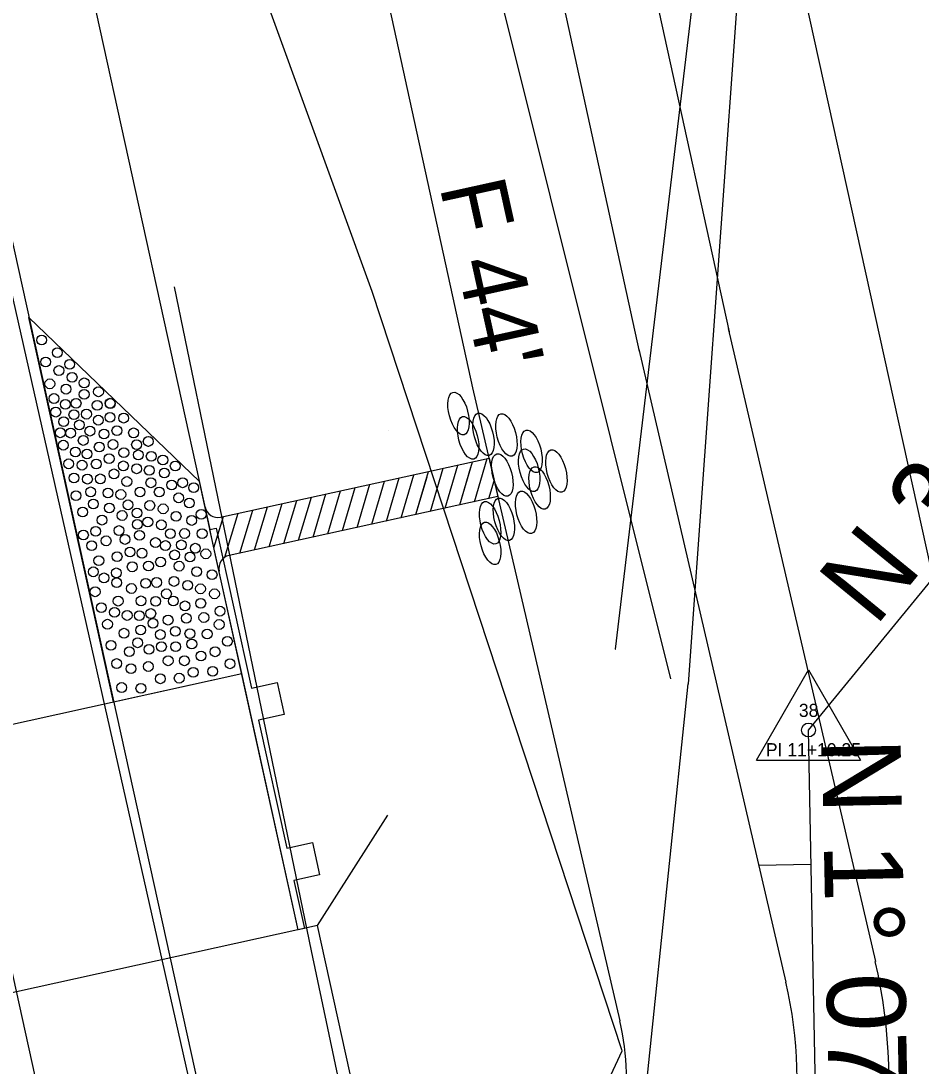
# Model space of a CAD drawing. Extents: x 2519952 to 2531965, y 848341 to 887632.
# Drawn here: x 2522935.4 to 2523004, y 863099 to 863178.7 of the extents above; entities that cross this region are included whole.
import ezdxf

# ---------------------------------------------------------------- set-up
doc = ezdxf.new("R2010")
doc.units = 0
for name, color, linetype in [('RD_EV_JW', 7, 'Continuous'), ('RD_EX_DV_Prop', 7, 'Continuous'), ('RD_EX_GuardRail', 7, 'Continuous'), ('RD_EX_H2O', 7, 'Continuous'), ('RD_EX_Misc', 7, 'Continuous'), ('RD_EX_Road', 7, 'Continuous'), ('RD_EX_RW', 7, 'Continuous'), ('RD_EX_VEG', 7, 'Continuous'), ('RD_HC_Cl', 7, 'Continuous'), ('RD_HC_Data', 7, 'Continuous'), ('RD_HC_Data_Tic', 7, 'Continuous'), ('RD_HC_txCode', 7, 'Continuous'), ('RD_PD_BCA', 7, 'Continuous'), ('RD_PD_Bridge', 7, 'Continuous'), ('RD_PD_CstnLmt', 7, 'Continuous'), ('RD_PD_DR_ErosCtrl', 7, 'Continuous'), ('RD_PD_Final_TrvlWay', 7, 'Continuous'), ('RD_PD_GR', 7, 'Continuous'), ('RD_PD_PaveShd', 7, 'Continuous'), ('RD_PD_TX_CstnLmt', 7, 'Continuous'), ('RD_SMD_Locator', 7, 'Continuous')]:
    doc.layers.add(name, color=color, linetype=linetype)

# ---------------------------------------------------------------- blocks, each defined once
blk = doc.blocks.new('TBC1')
at = {"layer": 'RD_PD_GR'}
blk.add_lwpolyline([(12.5, 2.5), (15, 2.5), (15, 0.492), (25, 0.492), (25, 2.5), (27.5, 2.5), (27.5, 0.492), (31.25, 0.492), (31.25, 0), (0, 0), (0, 0.492), (12.5, 0.492)], close=True, dxfattribs=at)

msp = doc.modelspace()

# ---------------------------------------------------------------- linework, layer by layer
at = {"layer": 'RD_EV_JW'}
msp.add_lwpolyline([(2522920.527, 863055.569), (2522967.569, 863070.747), (2522981.274, 863100.176), (2522962.21, 863158.087), (2522937.169, 863227.102), (2522907.556, 863365.862), (2522890.04, 863438.415), (2522867.996, 863538.839), (2522858.074, 863583.559), (2522887.186, 863587.355), (2522916.656, 863593.291)], dxfattribs=at)
at = {"layer": 'RD_EX_DV_Prop'}
msp.add_line((2522989.51, 863206.261), (2523054.026, 862913.28), dxfattribs=at)
at = {"layer": 'RD_EX_GuardRail'}
msp.add_lwpolyline([(2522963.145, 863081.451), (2522957.598, 863107.795), (2522947.155, 863158.431)], dxfattribs=at)
at = {"layer": 'RD_EX_H2O'}
for points in [[(2523224.216, 863086.689), (2523195.729, 863135.324), (2523216.583, 863174.261), (2523191.314, 863213.173), (2523142.614, 863247.836), (2523099.968, 863233.365), (2523064.196, 863226.552), (2523034.343, 863193.635), (2523009.678, 863201.78), (2522990.024, 863180.338), (2522986.288, 863128.151)], [(2522898.268, 863069.037), (2522903.054, 863060.382), (2522975.719, 863073.829), (2522981.786, 863084.838), (2522986.288, 863128.151)]]:
    msp.add_lwpolyline(points, dxfattribs=at)
at = {"layer": 'RD_EX_Misc'}
msp.add_lwpolyline([(2523225.665, 863086.89), (2523196.661, 863135.687), (2523217.305, 863174.605), (2523198.882, 863204.707), (2523192.281, 863214.105), (2523142.89, 863249.517), (2523099.598, 863234.813), (2523063.493, 863227.785), (2523034.22, 863194.205), (2523009.317, 863204.046), (2522987.011, 863183.473), (2522980.744, 863130.816)], dxfattribs=at)
at = {"layer": 'RD_EX_Road'}
msp.add_line((2522952.137, 863080.85), (2522930.599, 863176.326), dxfattribs=at)
at = {"layer": 'RD_EX_RW'}
msp.add_line((2522989.511, 863206.258), (2523054.026, 862913.278), dxfattribs=at)
at = {"layer": 'RD_EX_VEG'}
msp.add_lwpolyline([(2522984.982, 863128.55), (2522971.227, 863183.645), (2522892.381, 863575.764), (2522846.466, 863797.775)], dxfattribs=at)
at = {"layer": 'RD_HC_Cl'}
for p, q in [((2522800.525, 863715.741), (2523357.118, 861188.096)), ((2522995.466, 863124.639), (2523043.023, 863182.772)), ((2522996.539, 863069.862), (2522995.466, 863124.639))]:
    msp.add_line(p, q, dxfattribs=at)
at = {"layer": 'RD_HC_Data'}
for p, q in [((2522991.495, 863122.346), (2522995.467, 863129.226)), ((2522995.467, 863129.226), (2522999.435, 863122.346)), ((2522991.495, 863122.346), (2522999.435, 863122.346))]:
    msp.add_line(p, q, dxfattribs=at)
msp.add_circle((2522995.466, 863124.639), 0.529, dxfattribs=at)
at = {"layer": 'RD_HC_Data_Tic'}
msp.add_line((2522995.667, 863114.384), (2522991.667, 863114.306), dxfattribs=at)
at = {"layer": 'RD_PD_BCA'}
for p, q in [((2522984.06, 863179.459), (2522989.408, 863155.01)), ((2522989.352, 863155.259), (2523000.561, 863106.989))]:
    msp.add_line(p, q, dxfattribs=at)
msp.add_arc((2522961.597, 863097.941), 40, 282.41848, 13.07237, dxfattribs=at)
at = {"layer": 'RD_PD_Bridge'}
for p, q in [((2522909.296, 863119.48), (2522952.266, 863128.942)), ((2522956.567, 863109.41), (2522952.266, 863128.942)), ((2522958.032, 863109.733), (2522963.417, 863118.159))]:
    msp.add_line(p, q, dxfattribs=at)
for points in [[(2522958.032, 863109.733), (2522912.132, 863099.626)], [(2522985.989, 862982.775), (2522958.032, 863109.733)]]:
    msp.add_lwpolyline(points, dxfattribs=at)
at = {"layer": 'RD_PD_CstnLmt'}
for p, q in [((2522948.501, 863248.426), (2522969.87, 863150.736)), ((2522969.87, 863150.736), (2522981.079, 863102.465))]:
    msp.add_line(p, q, dxfattribs=at)
msp.add_arc((2522961.597, 863097.941), 20, 282.41848, 13.07237, dxfattribs=at)
at = {"layer": 'RD_PD_DR_ErosCtrl'}
for p, q in [((2522961.201, 863251.204), (2522982.57, 863153.514)), ((2522982.534, 863153.676), (2522993.742, 863105.405))]:
    msp.add_line(p, q, dxfattribs=at)
msp.add_arc((2522961.597, 863097.941), 33, 282.41848, 13.07237, dxfattribs=at)
at = {"layer": 'RD_PD_Final_TrvlWay'}
msp.add_line((2522901.104, 863314.786), (2523175.293, 862069.617), dxfattribs=at)
at = {"layer": 'RD_PD_GR'}
msp.add_line((2522901.461, 863359.665), (2522949.847, 863139.929), dxfattribs=at)
at = {"layer": 'RD_PD_PaveShd'}
for p, q in [((2522936.049, 863156.09), (2522949.041, 863143.592)), ((2522942.5, 863126.792), (2522936.049, 863156.09)), ((2522950.662, 863140.876), (2522971.117, 863145.369)), ((2522967.763, 863141.561), (2522968.747, 863144.849)), ((2522967.763, 863141.561), (2522968.747, 863144.849)), ((2522968.881, 863141.807), (2522969.865, 863145.094)), ((2522969.998, 863142.052), (2522970.982, 863145.34)), ((2522969.998, 863142.052), (2522970.982, 863145.34)), ((2522971.117, 863145.369), (2522971.795, 863142.447)), ((2522964.412, 863140.825), (2522965.395, 863144.113)), ((2522964.412, 863140.825), (2522965.395, 863144.113)), ((2522965.529, 863141.07), (2522966.513, 863144.358)), ((2522966.646, 863141.316), (2522967.63, 863144.603)), ((2522966.646, 863141.316), (2522967.63, 863144.603)), ((2522968.881, 863141.807), (2522969.743, 863144.689)), ((2522949.686, 863140.662), (2522949.041, 863143.592)), ((2522961.06, 863140.089), (2522962.044, 863143.376)), ((2522961.06, 863140.089), (2522962.044, 863143.376)), ((2522962.177, 863140.334), (2522963.161, 863143.622)), ((2522962.177, 863140.334), (2522963.161, 863143.622)), ((2522963.294, 863140.579), (2522964.278, 863143.867)), ((2522963.294, 863140.579), (2522964.278, 863143.867)), ((2522965.529, 863141.07), (2522966.391, 863143.953)), ((2522971.115, 863142.297), (2522971.518, 863143.642)), ((2522971.115, 863142.297), (2522971.518, 863143.642)), ((2522971.795, 863142.447), (2522951.308, 863137.947)), ((2522956.591, 863139.107), (2522957.575, 863142.395)), ((2522956.591, 863139.107), (2522957.575, 863142.395)), ((2522957.708, 863139.352), (2522958.692, 863142.64)), ((2522957.708, 863139.352), (2522958.692, 863142.64)), ((2522958.825, 863139.598), (2522959.809, 863142.885)), ((2522958.825, 863139.598), (2522959.809, 863142.885)), ((2522959.942, 863139.843), (2522960.926, 863143.131)), ((2522959.942, 863139.843), (2522960.926, 863143.131)), ((2522953.239, 863138.371), (2522954.223, 863141.658)), ((2522953.239, 863138.371), (2522954.223, 863141.658)), ((2522954.356, 863138.616), (2522955.34, 863141.904)), ((2522954.356, 863138.616), (2522955.34, 863141.904)), ((2522955.473, 863138.861), (2522956.457, 863142.149)), ((2522950.155, 863138.531), (2522950.871, 863140.922)), ((2522950.984, 863137.812), (2522951.988, 863141.167)), ((2522952.121, 863138.125), (2522953.105, 863141.413)), ((2522952.121, 863138.125), (2522953.105, 863141.413)), ((2522950.331, 863137.732), (2522949.686, 863140.662)), ((2522952.266, 863128.942), (2522950.331, 863137.732)), ((2522942.5, 863126.792), (2522952.266, 863128.942))]:
    msp.add_line(p, q, dxfattribs=at)
for centre in [(2522937.026, 863154.38), (2522938.215, 863153.422), (2522938.215, 863153.422), (2522937.328, 863152.707), (2522937.328, 863152.707), (2522939.153, 863152.527), (2522939.153, 863152.527), (2522938.336, 863152.051), (2522938.336, 863152.051), (2522937.644, 863151.041), (2522937.644, 863151.041), (2522939.341, 863151.538), (2522939.341, 863151.538), (2522940.263, 863151.112), (2522938.881, 863150.635), (2522938.881, 863150.635), (2522940.262, 863150.234), (2522940.262, 863150.234), (2522941.353, 863150.434), (2522941.353, 863150.434), (2522937.958, 863149.919), (2522937.958, 863149.919), (2522938.831, 863149.481), (2522938.831, 863149.481), (2522939.645, 863149.556), (2522939.645, 863149.556), (2522941.254, 863149.406), (2522941.254, 863149.406), (2522942.237, 863149.562), (2522942.261, 863149.538), (2522938.097, 863148.885), (2522938.097, 863148.885), (2522939.479, 863148.685), (2522939.479, 863148.685), (2522940.437, 863148.729), (2522940.437, 863148.729), (2522942.224, 863148.489), (2522942.224, 863148.489), (2522943.268, 863148.425), (2522943.268, 863148.425), (2522938.693, 863148.152), (2522938.693, 863148.152), (2522939.896, 863147.91), (2522939.896, 863147.91), (2522941.339, 863148.27), (2522941.339, 863148.27), (2522938.44, 863147.306), (2522938.44, 863147.306), (2522939.235, 863147.281), (2522939.235, 863147.281), (2522940.699, 863147.434), (2522940.699, 863147.434), (2522941.77, 863147.208), (2522941.77, 863147.208), (2522942.756, 863147.474), (2522942.756, 863147.474), (2522944.027, 863147.3), (2522944.027, 863147.3), (2522938.676, 863146.361), (2522938.676, 863146.361), (2522940.191, 863146.723), (2522940.191, 863146.723), (2522941.41, 863146.217), (2522941.41, 863146.217), (2522942.453, 863146.413), (2522942.453, 863146.413), (2522944.255, 863146.405), (2522944.255, 863146.405), (2522945.145, 863146.647), (2522945.156, 863146.645), (2522939.595, 863145.838), (2522939.595, 863145.838), (2522940.473, 863145.694), (2522940.473, 863145.694), (2522942.164, 863145.329), (2522942.164, 863145.329), (2522943.284, 863145.786), (2522943.284, 863145.786), (2522944.392, 863145.62), (2522944.392, 863145.62), (2522945.373, 863145.513), (2522945.373, 863145.513), (2522946.259, 863145.227), (2522946.259, 863145.227), (2522939.082, 863144.94), (2522939.082, 863144.94), (2522940.102, 863144.836), (2522940.102, 863144.836), (2522941.181, 863144.926), (2522941.181, 863144.926), (2522943.252, 863144.782), (2522943.252, 863144.782), (2522944.262, 863144.563), (2522944.262, 863144.563), (2522945.218, 863144.443), (2522945.218, 863144.443), (2522947.201, 863144.78), (2522947.201, 863144.78), (2522939.482, 863143.863), (2522939.482, 863143.863), (2522940.51, 863143.773), (2522940.51, 863143.773), (2522941.487, 863143.791), (2522941.487, 863143.791), (2522942.531, 863144.171), (2522942.531, 863144.171), (2522946.377, 863144.241), (2522946.377, 863144.241), (2522943.514, 863143.588), (2522943.514, 863143.588), (2522945.347, 863143.494), (2522945.347, 863143.494), (2522946.932, 863143.331), (2522946.932, 863143.331), (2522947.767, 863143.494), (2522947.767, 863143.494), (2522948.606, 863143.12), (2522948.606, 863143.12), (2522948.606, 863143.12), (2522939.637, 863142.514), (2522939.637, 863142.514), (2522940.756, 863142.8), (2522940.756, 863142.8), (2522942.075, 863142.716), (2522942.075, 863142.716), (2522943.053, 863142.599), (2522943.053, 863142.599), (2522944.517, 863142.792), (2522944.517, 863142.792), (2522945.983, 863142.787), (2522945.983, 863142.787), (2522947.464, 863142.345), (2522947.464, 863142.345), (2522940.151, 863141.265), (2522940.151, 863141.265), (2522940.957, 863141.882), (2522940.957, 863141.882), (2522942.185, 863141.566), (2522942.185, 863141.566), (2522943.604, 863141.814), (2522943.604, 863141.814), (2522945.263, 863141.762), (2522945.263, 863141.762), (2522946.283, 863141.509), (2522946.283, 863141.509), (2522948.278, 863141.956), (2522948.278, 863141.956), (2522941.621, 863140.649), (2522941.621, 863140.649), (2522943.152, 863140.998), (2522943.152, 863140.998), (2522944.287, 863141.196), (2522944.287, 863141.196), (2522945.114, 863140.504), (2522945.114, 863140.504), (2522947.269, 863140.935), (2522947.269, 863140.935), (2522948.457, 863140.621), (2522948.457, 863140.621), (2522949.18, 863141.087), (2522949.18, 863141.087), (2522941.137, 863139.792), (2522941.137, 863139.792), (2522942.912, 863139.85), (2522942.912, 863139.85), (2522944.314, 863140.32), (2522944.314, 863140.32), (2522946.145, 863140.289), (2522946.145, 863140.289), (2522946.833, 863139.618), (2522946.833, 863139.618), (2522947.911, 863139.627), (2522947.911, 863139.627), (2522949.252, 863139.618), (2522949.252, 863139.618), (2522940.205, 863139.512), (2522940.205, 863139.512), (2522941.933, 863139.068), (2522941.933, 863139.068), (2522943.371, 863139.175), (2522943.371, 863139.175), (2522944.477, 863139.485), (2522944.477, 863139.485), (2522945.698, 863138.934), (2522945.698, 863138.934), (2522940.832, 863138.704), (2522940.832, 863138.704), (2522943.759, 863138.214), (2522943.759, 863138.214), (2522944.67, 863138.125), (2522944.67, 863138.125), (2522946.457, 863138.707), (2522946.457, 863138.707), (2522947.671, 863138.758), (2522947.671, 863138.758), (2522948.732, 863138.502), (2522948.732, 863138.502), (2522949.535, 863138.076), (2522949.535, 863138.076), (2522941.378, 863137.559), (2522941.378, 863137.559), (2522942.772, 863137.866), (2522942.772, 863137.866), (2522946.082, 863137.455), (2522946.082, 863137.455), (2522947.152, 863137.997), (2522947.152, 863137.997), (2522948.323, 863137.833), (2522948.323, 863137.833), (2522940.954, 863136.704), (2522942.71, 863136.623), (2522942.71, 863136.623), (2522943.925, 863137.087), (2522943.925, 863137.087), (2522945.164, 863137.151), (2522945.164, 863137.151), (2522947.496, 863137.135), (2522947.496, 863137.135), (2522948.837, 863136.714), (2522948.837, 863136.714), (2522950.01, 863136.487), (2522950.01, 863136.487), (2522941.769, 863136.243), (2522941.769, 863136.243), (2522942.734, 863135.872), (2522942.734, 863135.872), (2522944.954, 863135.828), (2522944.954, 863135.828), (2522945.779, 863135.892), (2522945.779, 863135.892), (2522947.105, 863135.97), (2522947.105, 863135.97), (2522948.155, 863135.677), (2522948.155, 863135.677), (2522941.1, 863135.182), (2522941.1, 863135.182), (2522943.863, 863135.431), (2522943.863, 863135.431), (2522946.533, 863135.025), (2522946.533, 863135.025), (2522949.128, 863135.407), (2522949.128, 863135.407), (2522950.193, 863135.026), (2522950.193, 863135.026), (2522942.852, 863134.472), (2522942.852, 863134.472), (2522944.594, 863134.489), (2522944.594, 863134.489), (2522945.708, 863134.458), (2522945.708, 863134.458), (2522947.051, 863134.477), (2522947.051, 863134.477), (2522947.952, 863134.105), (2522947.952, 863134.105), (2522949.15, 863134.305), (2522949.15, 863134.305), (2522941.564, 863133.968), (2522941.564, 863133.968), (2522942.574, 863133.619), (2522942.574, 863133.619), (2522943.537, 863133.378), (2522943.537, 863133.378), (2522944.462, 863133.364), (2522944.462, 863133.364), (2522945.338, 863133.522), (2522945.338, 863133.522), (2522950.608, 863133.703), (2522950.608, 863133.703), (2522942.04, 863132.71), (2522942.04, 863132.71), (2522945.502, 863132.779), (2522946.657, 863133.024), (2522946.657, 863133.024), (2522948.044, 863133.167), (2522948.044, 863133.167), (2522949.383, 863133.222), (2522949.383, 863133.222), (2522950.552, 863132.686), (2522950.552, 863132.686), (2522943.302, 863132.022), (2522943.302, 863132.022), (2522944.573, 863132.262), (2522944.573, 863132.262), (2522946.063, 863131.92), (2522946.063, 863131.92), (2522947.211, 863132.172), (2522947.211, 863132.172), (2522948.317, 863131.99), (2522948.317, 863131.99), (2522949.634, 863131.968), (2522949.634, 863131.968), (2522942.302, 863131.101), (2522942.302, 863131.101), (2522944.338, 863131.292), (2522944.338, 863131.292), (2522946.152, 863130.998), (2522946.152, 863130.998), (2522947.232, 863130.991), (2522947.232, 863130.991), (2522948.465, 863131.195), (2522948.465, 863131.195), (2522951.18, 863131.403), (2522951.18, 863131.403), (2522943.708, 863130.619), (2522943.708, 863130.619), (2522945.207, 863130.791), (2522945.207, 863130.791), (2522949.171, 863130.287), (2522949.171, 863130.287), (2522950.239, 863130.609), (2522950.239, 863130.609), (2522942.734, 863129.711), (2522942.734, 863129.711), (2522943.836, 863129.319), (2522943.836, 863129.319), (2522945.147, 863129.485), (2522945.147, 863129.485), (2522946.663, 863129.921), (2522946.663, 863129.921), (2522947.904, 863129.922), (2522947.904, 863129.922), (2522951.371, 863129.692), (2522951.371, 863129.692), (2522951.371, 863129.692), (2522946.066, 863128.549), (2522946.066, 863128.549), (2522947.506, 863128.594), (2522947.506, 863128.594), (2522948.57, 863129.041), (2522948.57, 863129.041), (2522950.06, 863129.112), (2522950.06, 863129.112), (2522943.116, 863127.881), (2522943.116, 863127.881), (2522944.584, 863127.814), (2522944.584, 863127.814)]:
    msp.add_circle(centre, 0.375, dxfattribs=at)
for centre, start, end in [((2522950.447, 863141.853), 192.41848, 282.38886), ((2522951.523, 863136.97), 102.38886, 192.41848)]:
    msp.add_arc(centre, 1, start, end, dxfattribs=at)
for centre in [(2522968.795, 863148.772), (2522970.699, 863147.189), (2522970.699, 863147.189), (2522972.443, 863147.144), (2522972.443, 863147.144), (2522969.523, 863146.922), (2522974.363, 863145.888), (2522974.363, 863145.888), (2522972.132, 863144.087), (2522972.132, 863144.087), (2522974.181, 863144.453), (2522974.181, 863144.453), (2522976.252, 863144.393), (2522976.252, 863144.393), (2522974.975, 863143.1), (2522974.975, 863143.1), (2522972.252, 863140.708), (2522972.252, 863140.708), (2522973.941, 863141.238), (2522973.941, 863141.238), (2522971.198, 863140.443), (2522971.198, 863140.443), (2522971.205, 863138.871), (2522971.205, 863138.871)]:
    msp.add_ellipse(centre, major_axis=(-0.426, 1.616), ratio=0.429445, dxfattribs=at)
at = {"layer": 'RD_SMD_Locator'}
for centre in [(2522947.155, 863158.431), (2522962.21, 863158.087), (2522963.428, 863147.503), (2522980.744, 863130.816), (2522984.982, 863128.55), (2522986.288, 863128.151), (2522986.288, 863128.151), (2522995.466, 863124.639), (2522957.598, 863107.795), (2522981.274, 863100.176)]:
    msp.add_circle(centre, 0.001, dxfattribs=at)

# ---------------------------------------------------------------- block references
at = {"layer": 'RD_PD_Bridge', "rotation": -77.58151740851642}
msp.add_blockref('TBC1', (2522949.847, 863139.929), dxfattribs=at)

# ---------------------------------------------------------------- texts
at = {"layer": 'RD_HC_Data'}
for s, rotation, p in [('N 39%%d 17\' 08" E', 50.71443, (2523000.555, 863132.439)), ('N 1%%d 07\' 21" W', 271.12261, (2522996.479, 863123.979))]:
    msp.add_text(s, height=6, rotation=rotation, dxfattribs=at).set_placement(p)
at = {"layer": 'RD_HC_txCode'}
for s, p in [('38', (2522994.733, 863125.639)), ('PI 11+10.25', (2522992.214, 863122.639))]:
    msp.add_text(s, height=1, dxfattribs=at).set_placement(p)
at = {"layer": 'RD_PD_TX_CstnLmt'}
msp.add_text("F 44'", height=5, rotation=282.41848, dxfattribs=at).set_placement((2522967.336, 863166.094))

doc.saveas('drawing.dxf')
